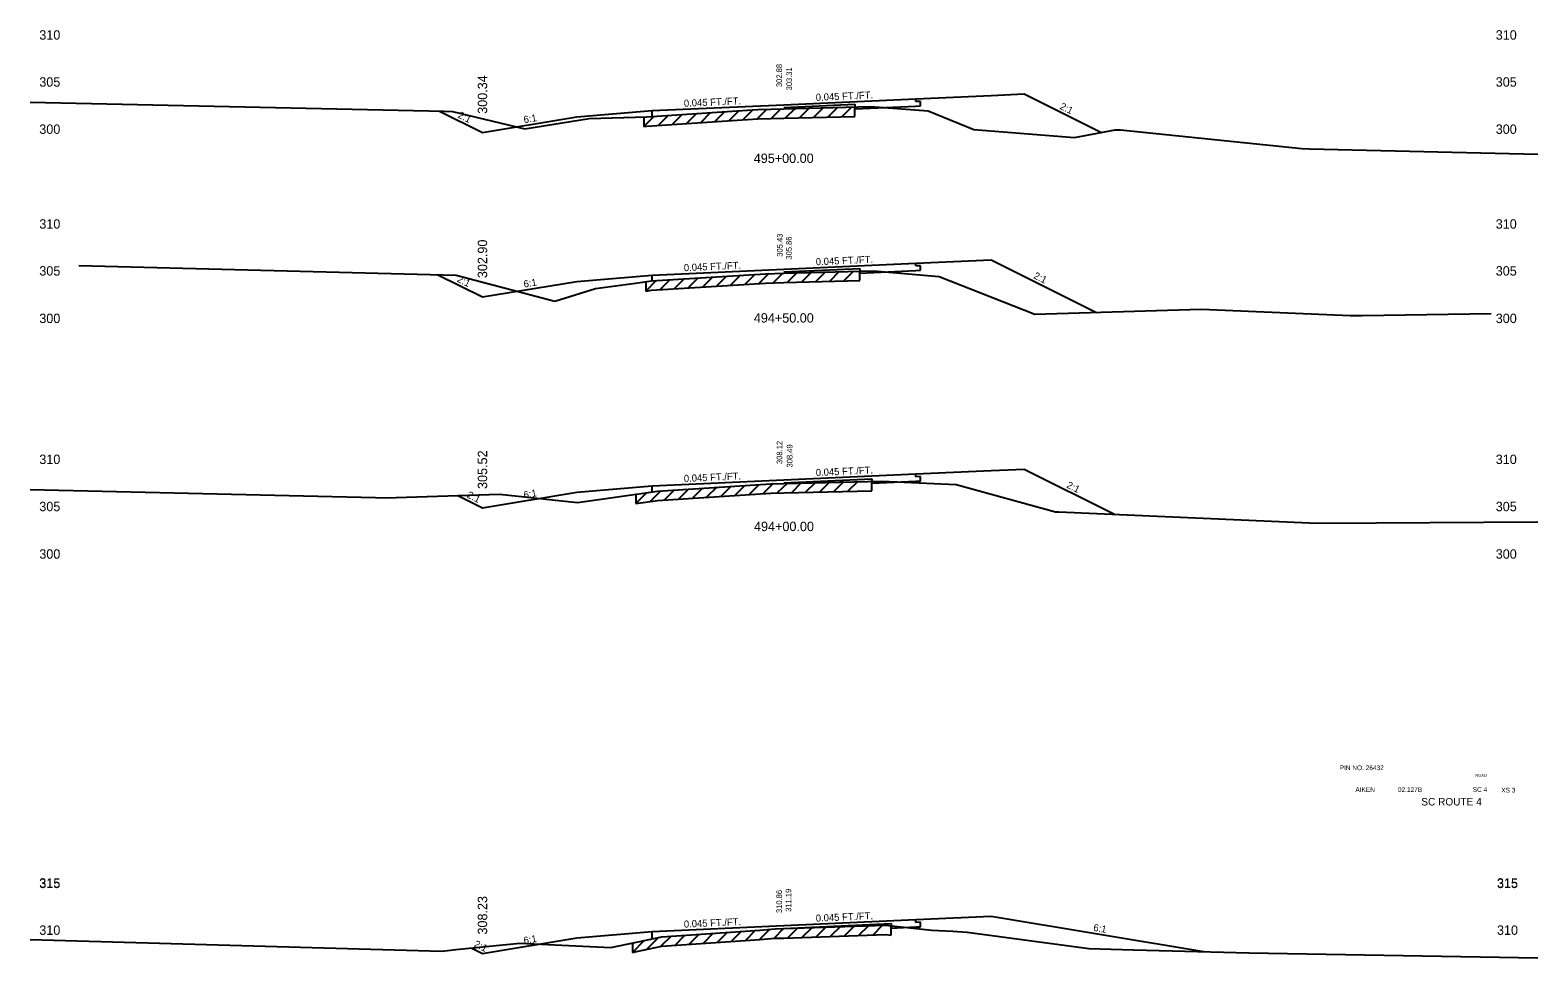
# Model space of a CAD drawing. Extents: x 883 to 1160, y 1002 to 4323.
# Drawn here: x 1000 to 1160, y 1312.8 to 1411.2 of the extents above; entities that cross this region are included whole.
import ezdxf

# ---------------------------------------------------------------- set-up
doc = ezdxf.new("R2010")
doc.units = 0
for name, color, linetype in [('Level 1', 7, 'Continuous'), ('Level 10', 7, 'Continuous'), ('Level 11', 7, 'Continuous'), ('Level 12', 7, 'Continuous'), ('Level 3', 7, 'Continuous'), ('Level 32', 7, 'Continuous'), ('Level 33', 7, 'Continuous'), ('Level 53', 7, 'Continuous'), ('Level 59', 7, 'Continuous'), ('Level 6', 7, 'Continuous'), ('Level 60', 7, 'Continuous'), ('Level 61', 7, 'Continuous'), ('Level 7', 7, 'Continuous')]:
    doc.layers.add(name, color=color, linetype=linetype)

msp = doc.modelspace()

# ---------------------------------------------------------------- linework, layer by layer
at = {"layer": 'Level 11'}
for p, q in [((1094, 1403.64), (1094, 1403.94)), ((1094.5, 1403.66), (1094, 1403.64)), ((1094.5, 1403.18), (1094.5, 1403.66)), ((1066, 1402.06), (1066, 1402.68)), ((1094, 1403.16), (1094.5, 1403.18)), ((1094, 1386.19), (1094, 1386.49)), ((1094.5, 1386.21), (1094, 1386.19)), ((1094, 1385.71), (1094.5, 1385.73)), ((1094.5, 1385.73), (1094.5, 1386.21)), ((1066, 1384.61), (1066, 1385.23)), ((1094, 1363.82), (1094, 1364.12)), ((1094.5, 1363.84), (1094, 1363.82)), ((1094, 1363.34), (1094.5, 1363.36)), ((1094.5, 1363.36), (1094.5, 1363.84)), ((1066, 1362.21), (1066, 1362.86)), ((1094, 1316.52), (1094, 1316.82)), ((1066, 1314.77), (1066, 1315.56)), ((1094.5, 1316.54), (1094, 1316.52)), ((1094, 1316.04), (1094.5, 1316.06)), ((1094.5, 1316.06), (1094.5, 1316.54))]:
    msp.add_line(p, q, dxfattribs=at)
at = {"layer": 'Level 12'}
for p, q in [((1087.51, 1402.87), (1094, 1403.16)), ((1087.51, 1403.07), (1087.51, 1402.87)), ((1088.03, 1385.44), (1094, 1385.71)), ((1088.03, 1385.65), (1088.03, 1385.44)), ((1089.31, 1363.34), (1089.31, 1363.13)), ((1089.31, 1363.13), (1094, 1363.34)), ((1091.36, 1316.16), (1091.36, 1315.92)), ((1091.36, 1315.92), (1094, 1316.04))]:
    msp.add_line(p, q, dxfattribs=at)
at = {"layer": 'Level 53'}
for p, q in [((1080, 1403.01), (1087.51, 1403.35)), ((1087.51, 1403.35), (1087.51, 1403.07)), ((1080, 1385.56), (1088.03, 1385.92)), ((1088.03, 1385.92), (1088.03, 1385.65)), ((1080, 1363.19), (1089.31, 1363.61)), ((1089.31, 1363.61), (1089.31, 1363.34)), ((1080, 1315.89), (1091.36, 1316.4)), ((1091.36, 1316.4), (1091.36, 1316.16))]:
    msp.add_line(p, q, dxfattribs=at)
at = {"layer": 'Level 59'}
for p, q in [((1066, 1402.68), (1080, 1403.31)), ((1080, 1403.31), (1094, 1403.94)), ((1066, 1385.23), (1080, 1385.86)), ((1080, 1385.86), (1094, 1386.49)), ((1066, 1362.86), (1080, 1363.49)), ((1080, 1363.49), (1094, 1364.12)), ((1080, 1316.19), (1094, 1316.82)), ((1066, 1315.56), (1080, 1316.19))]:
    msp.add_line(p, q, dxfattribs=at)
at = {"layer": 'Level 6'}
for p, q in [((1094, 1403.94), (1102, 1404.3)), ((1102, 1404.3), (1105.5, 1404.46)), ((1058, 1402.01), (1066, 1402.68)), ((1094, 1386.49), (1102, 1386.85)), ((1058, 1384.56), (1066, 1385.23)), ((1094, 1364.12), (1102, 1364.48)), ((1102, 1364.48), (1105.5, 1364.64)), ((1058, 1362.19), (1066, 1362.86)), ((1094, 1316.82), (1102, 1317.18)), ((1058, 1314.89), (1066, 1315.56))]:
    msp.add_line(p, q, dxfattribs=at)
at = {"layer": 'Level 60'}
for p, q in [((1000, 1403.58), (1043.93, 1402.62)), ((1043.93, 1402.62), (1044.82, 1402.57)), ((1044.82, 1402.57), (1052.51, 1400.75)), ((1052.51, 1400.75), (1059.32, 1401.83)), ((1059.32, 1401.83), (1065.44, 1402.02)), ((1065.44, 1402.02), (1075.04, 1402.66)), ((1075.04, 1402.66), (1077.22, 1402.8)), ((1077.22, 1402.8), (1080, 1402.88)), ((1080, 1402.88), (1089.19, 1403.11)), ((1089.19, 1403.11), (1095.29, 1402.67)), ((1095.29, 1402.67), (1100.15, 1400.67)), ((1100.15, 1400.67), (1110.82, 1399.84)), ((1110.82, 1399.84), (1115.14, 1400.63)), ((1115.14, 1400.63), (1115.71, 1400.65)), ((1115.71, 1400.65), (1134.97, 1398.67)), ((1134.97, 1398.67), (1135.76, 1398.64)), ((1135.76, 1398.64), (1160, 1398.05)), ((1005.18, 1386.24), (1045.2, 1385.21)), ((1080, 1385.43), (1089.51, 1385.69)), ((1089.51, 1385.69), (1096.47, 1385.06)), ((1045.2, 1385.21), (1055.69, 1382.45)), ((1060, 1383.81), (1064.24, 1384.38)), ((1064.24, 1384.38), (1065.93, 1384.61)), ((1065.93, 1384.61), (1078.04, 1385.37)), ((1078.04, 1385.37), (1080, 1385.43)), ((1096.47, 1385.06), (1106.61, 1381.06)), ((1055.69, 1382.45), (1060, 1383.81)), ((1106.61, 1381.06), (1124.24, 1381.62)), ((1124.24, 1381.62), (1125.15, 1381.58)), ((1125.15, 1381.58), (1140.1, 1380.93)), ((1140.1, 1380.93), (1141.4, 1380.93)), ((1141.4, 1380.93), (1155.03, 1381.13)), ((1080, 1363.12), (1090.37, 1363.36)), ((1090.37, 1363.36), (1098.28, 1363)), ((1000, 1362.48), (1036.65, 1361.62)), ((1036.65, 1361.62), (1037.73, 1361.59)), ((1037.73, 1361.59), (1049.82, 1361.96)), ((1049.82, 1361.96), (1058.07, 1361.07)), ((1058.07, 1361.07), (1066.59, 1362.3)), ((1066.59, 1362.3), (1078.61, 1363.08)), ((1078.61, 1363.08), (1080, 1363.12)), ((1098.28, 1363), (1108.81, 1360.09)), ((1108.81, 1360.09), (1109.15, 1360.08)), ((1109.15, 1360.08), (1135.76, 1358.93)), ((1135.76, 1358.93), (1137.1, 1358.91)), ((1137.1, 1358.91), (1160, 1359.04)), ((1067.05, 1314.99), (1077.42, 1315.71)), ((1077.42, 1315.71), (1079.05, 1315.83)), ((1079.05, 1315.83), (1080, 1315.86)), ((1080, 1315.86), (1090.77, 1316.22)), ((1090.77, 1316.22), (1095.69, 1315.71)), ((1095.69, 1315.71), (1097.9, 1315.58)), ((1097.9, 1315.58), (1099.45, 1315.49)), ((1099.45, 1315.49), (1109.2, 1314.18)), ((1000, 1314.7), (1038.67, 1313.62)), ((1038.67, 1313.62), (1043.72, 1313.48)), ((1043.72, 1313.48), (1045.19, 1313.63)), ((1045.19, 1313.63), (1051.95, 1314.3)), ((1051.95, 1314.3), (1061.63, 1313.87)), ((1061.63, 1313.87), (1064.36, 1314.43)), ((1064.36, 1314.43), (1067.05, 1314.99)), ((1109.2, 1314.18), (1112.36, 1313.75)), ((1112.36, 1313.75), (1117.1, 1313.62)), ((1117.1, 1313.62), (1129.35, 1313.29)), ((1129.35, 1313.29), (1160, 1312.76))]:
    msp.add_line(p, q, dxfattribs=at)
at = {"layer": 'Level 61'}
for p, q in [((1066.2, 1402.07), (1065.14, 1401.01)), ((1065.14, 1402.01), (1065.14, 1401.01)), ((1065.44, 1401.02), (1075.04, 1401.66)), ((1067.71, 1402.17), (1066.64, 1401.1)), ((1069.21, 1402.27), (1068.14, 1401.2)), ((1070.71, 1402.37), (1069.64, 1401.3)), ((1072.21, 1402.47), (1071.14, 1401.4)), ((1073.71, 1402.57), (1072.64, 1401.5)), ((1075.21, 1402.67), (1074.14, 1401.6)), ((1075.04, 1401.66), (1077.22, 1401.8)), ((1076.71, 1402.77), (1075.64, 1401.7)), ((1078.17, 1402.83), (1077.14, 1401.8)), ((1077.22, 1401.8), (1080, 1401.88)), ((1079.67, 1402.87), (1078.64, 1401.84)), ((1080, 1401.88), (1087.51, 1402.07)), ((1081.17, 1402.91), (1080.14, 1401.88)), ((1082.67, 1402.94), (1081.64, 1401.92)), ((1084.17, 1402.98), (1083.14, 1401.96)), ((1085.67, 1403.02), (1084.64, 1401.99)), ((1087.17, 1403.06), (1086.14, 1402.03)), ((1087.51, 1402.07), (1087.51, 1403.07)), ((1065.14, 1401.01), (1065.44, 1401.02)), ((1087.37, 1385.63), (1086.34, 1384.6)), ((1088.03, 1384.65), (1088.03, 1385.65)), ((1066.45, 1384.64), (1065.34, 1383.53)), ((1065.34, 1384.53), (1065.34, 1383.53)), ((1065.93, 1383.61), (1078.04, 1384.37)), ((1067.9, 1384.73), (1066.84, 1383.67)), ((1069.4, 1384.83), (1068.34, 1383.76)), ((1070.9, 1384.92), (1069.84, 1383.86)), ((1072.4, 1385.02), (1071.34, 1383.95)), ((1073.9, 1385.11), (1072.84, 1384.05)), ((1075.4, 1385.21), (1074.34, 1384.14)), ((1076.9, 1385.3), (1075.84, 1384.23)), ((1078.39, 1385.38), (1077.34, 1384.33)), ((1078.04, 1384.37), (1080, 1384.43)), ((1079.87, 1385.42), (1078.84, 1384.4)), ((1080, 1384.43), (1088.03, 1384.65)), ((1081.37, 1385.46), (1080.34, 1384.44)), ((1082.87, 1385.51), (1081.84, 1384.48)), ((1084.37, 1385.55), (1083.34, 1384.52)), ((1085.87, 1385.59), (1084.84, 1384.56)), ((1065.34, 1383.53), (1065.93, 1383.61)), ((1084.82, 1363.23), (1083.79, 1362.21)), ((1086.32, 1363.27), (1085.29, 1362.24)), ((1087.82, 1363.3), (1086.79, 1362.28)), ((1089.31, 1362.34), (1089.31, 1363.34)), ((1065.46, 1362.14), (1064.29, 1360.97)), ((1064.29, 1361.97), (1064.29, 1360.97)), ((1066.93, 1362.32), (1065.79, 1361.18)), ((1066.59, 1361.3), (1078.61, 1362.08)), ((1068.36, 1362.41), (1067.29, 1361.34)), ((1069.86, 1362.51), (1068.79, 1361.44)), ((1071.36, 1362.61), (1070.29, 1361.54)), ((1072.86, 1362.71), (1071.79, 1361.64)), ((1074.36, 1362.8), (1073.29, 1361.74)), ((1075.86, 1362.9), (1074.79, 1361.83)), ((1077.36, 1363), (1076.29, 1361.93)), ((1078.85, 1363.09), (1077.79, 1362.03)), ((1078.61, 1362.08), (1080, 1362.12)), ((1080.32, 1363.12), (1079.29, 1362.1)), ((1080, 1362.12), (1089.31, 1362.34)), ((1081.82, 1363.16), (1080.79, 1362.13)), ((1083.32, 1363.19), (1082.29, 1362.17)), ((1064.29, 1360.97), (1066.59, 1361.3)), ((1070.99, 1315.26), (1069.91, 1314.19)), ((1072.49, 1315.37), (1071.41, 1314.29)), ((1073.99, 1315.47), (1072.91, 1314.4)), ((1075.49, 1315.58), (1074.41, 1314.5)), ((1076.99, 1315.68), (1075.91, 1314.61)), ((1078.49, 1315.79), (1077.41, 1314.71)), ((1079.95, 1315.86), (1078.91, 1314.82)), ((1080, 1314.86), (1090.77, 1315.22)), ((1081.45, 1315.91), (1080.41, 1314.87)), ((1082.95, 1315.96), (1081.91, 1314.93)), ((1084.45, 1316.01), (1083.41, 1314.98)), ((1085.95, 1316.06), (1084.91, 1315.03)), ((1087.45, 1316.11), (1086.41, 1315.08)), ((1088.95, 1316.16), (1087.91, 1315.13)), ((1090.45, 1316.21), (1089.41, 1315.18)), ((1090.77, 1315.22), (1091.36, 1315.16)), ((1091.36, 1315.16), (1091.36, 1316.16)), ((1065.17, 1314.6), (1063.91, 1313.34)), ((1063.91, 1314.34), (1063.91, 1313.34)), ((1064.36, 1313.43), (1067.05, 1313.99)), ((1066.67, 1314.91), (1065.41, 1313.65)), ((1068.01, 1315.06), (1066.91, 1313.96)), ((1067.05, 1313.99), (1077.42, 1314.71)), ((1069.49, 1315.16), (1068.41, 1314.08)), ((1077.42, 1314.71), (1079.05, 1314.83)), ((1079.05, 1314.83), (1080, 1314.86)), ((1063.91, 1313.34), (1064.36, 1313.43))]:
    msp.add_line(p, q, dxfattribs=at)
at = {"layer": 'Level 7'}
for p, q in [((1105.5, 1404.46), (1113.68, 1400.36)), ((1043.43, 1402.63), (1048, 1400.34)), ((1048, 1400.34), (1058, 1402.01)), ((1102, 1386.85), (1113.17, 1381.27)), ((1043.27, 1385.26), (1048, 1382.9)), ((1048, 1382.9), (1058, 1384.56)), ((1105.5, 1364.64), (1115.13, 1359.82)), ((1045.4, 1361.82), (1048, 1360.52)), ((1048, 1360.52), (1058, 1362.19)), ((1102, 1317.18), (1124.54, 1313.42)), ((1046.86, 1313.79), (1048, 1313.23)), ((1048, 1313.23), (1058, 1314.89))]:
    msp.add_line(p, q, dxfattribs=at)

# ---------------------------------------------------------------- texts
at = {"layer": 'Level 1'}
for s, height, p in [('495+00.00', 1, (1076.79, 1397.12)), ('494+50.00', 1, (1076.8, 1380.18)), ('494+00.00', 1, (1076.82, 1358.05)), ('PIN NO. 26432', 0.5, (1138.97, 1332.68)), ('AIKEN', 0.5, (1140.64, 1330.37)), ('02.127B', 0.5, (1145.15, 1330.37)), ('SC ROUTE 4', 0.8, (1147.63, 1328.93)), ('SC 4', 0.5, (1153.09, 1330.37)), ('XS 3', 0.5, (1156.12, 1330.31))]:
    msp.add_text(s, height=height, dxfattribs=at).set_placement(p)
at = {"layer": 'Level 10'}
for s, p in [('302.88', (1079.79, 1405.18)), ('305.43', (1079.85, 1387.17)), ('308.12', (1079.82, 1365.17)), ('310.86', (1079.79, 1317.51))]:
    msp.add_text(s, height=0.6, rotation=90, dxfattribs=at).set_placement(p)
at = {"layer": 'Level 3'}
for s, height, p in [(' 310', 1, (1000.6, 1410.21)), (' 310', 1, (1155.16, 1410.21)), (' 305', 1, (1000.6, 1405.22)), (' 305', 1, (1155.16, 1405.22)), (' 300', 1, (1000.6, 1400.21)), (' 300', 1, (1155.16, 1400.21)), (' 310', 1, (1000.6, 1390.15)), (' 310', 1, (1155.16, 1390.15)), (' 305', 1, (1000.6, 1385.17)), (' 305', 1, (1155.16, 1385.17)), (' 300', 1, (1000.6, 1380.13)), (' 300', 1, (1155.16, 1380.13)), (' 310', 1, (1000.6, 1365.17)), (' 310', 1, (1155.16, 1365.17)), (' 305', 1, (1000.6, 1360.16)), (' 305', 1, (1155.16, 1360.16)), (' 300', 1, (1000.6, 1355.12)), (' 300', 1, (1155.16, 1355.12)), ('ROAD', 0.3, (1153.38, 1331.96)), (' 315', 1, (1000.6, 1320.21)), (' 315', 1, (1000.6, 1320.16)), (' 315', 1, (1155.29, 1320.21)), (' 315', 1, (1155.29, 1320.16)), (' 310', 1, (1000.6, 1315.2)), (' 310', 1, (1155.29, 1315.2))]:
    msp.add_text(s, height=height, dxfattribs=at).set_placement(p)
at = {"layer": 'Level 32'}
for s, rotation, p in [('0.045 FT./FT.', 2.5766, (1069.39, 1403.08)), ('0.045 FT./FT.', 2.5766, (1083.39, 1403.71)), ('2:1', 333.435, (1109.2, 1402.89)), ('2:1', 333.435, (1045.32, 1401.97)), ('6:1', 9.4623, (1052.43, 1401.34)), ('0.045 FT./FT.', 2.5766, (1083.39, 1386.26)), ('0.045 FT./FT.', 2.5766, (1069.39, 1385.63)), ('2:1', 333.435, (1045.24, 1384.56)), ('6:1', 9.4623, (1052.43, 1383.89)), ('2:1', 333.435, (1106.42, 1384.92)), ('0.045 FT./FT.', 2.5766, (1083.39, 1363.89)), ('0.045 FT./FT.', 2.5766, (1069.39, 1363.26)), ('2:1', 333.435, (1109.92, 1362.7)), ('2:1', 333.435, (1046.3, 1361.65)), ('6:1', 9.4623, (1052.43, 1361.52)), ('0.045 FT./FT.', 2.5766, (1069.39, 1315.96)), ('0.045 FT./FT.', 2.5766, (1083.39, 1316.59)), ('6:1', 350.5377, (1112.79, 1315.63)), ('2:1', 333.435, (1047.04, 1313.99)), ('6:1', 9.4623, (1052.43, 1314.22))]:
    msp.add_text(s, height=0.75, rotation=rotation, dxfattribs=at).set_placement(p)
at = {"layer": 'Level 33'}
for s, p in [('300.34', (1048.5, 1402.34)), ('302.90', (1048.5, 1384.9)), ('305.52', (1048.5, 1362.52)), ('308.23', (1048.5, 1315.23))]:
    msp.add_text(s, height=1, rotation=90, dxfattribs=at).set_placement(p)
at = {"layer": 'Level 59'}
for s, p in [(' 303.31', (1080.84, 1404.6)), (' 305.86', (1080.82, 1386.64)), (' 308.49', (1080.9, 1364.58)), (' 311.19', (1080.77, 1317.42))]:
    msp.add_text(s, height=0.6, rotation=90, dxfattribs=at).set_placement(p)

doc.saveas('drawing.dxf')
